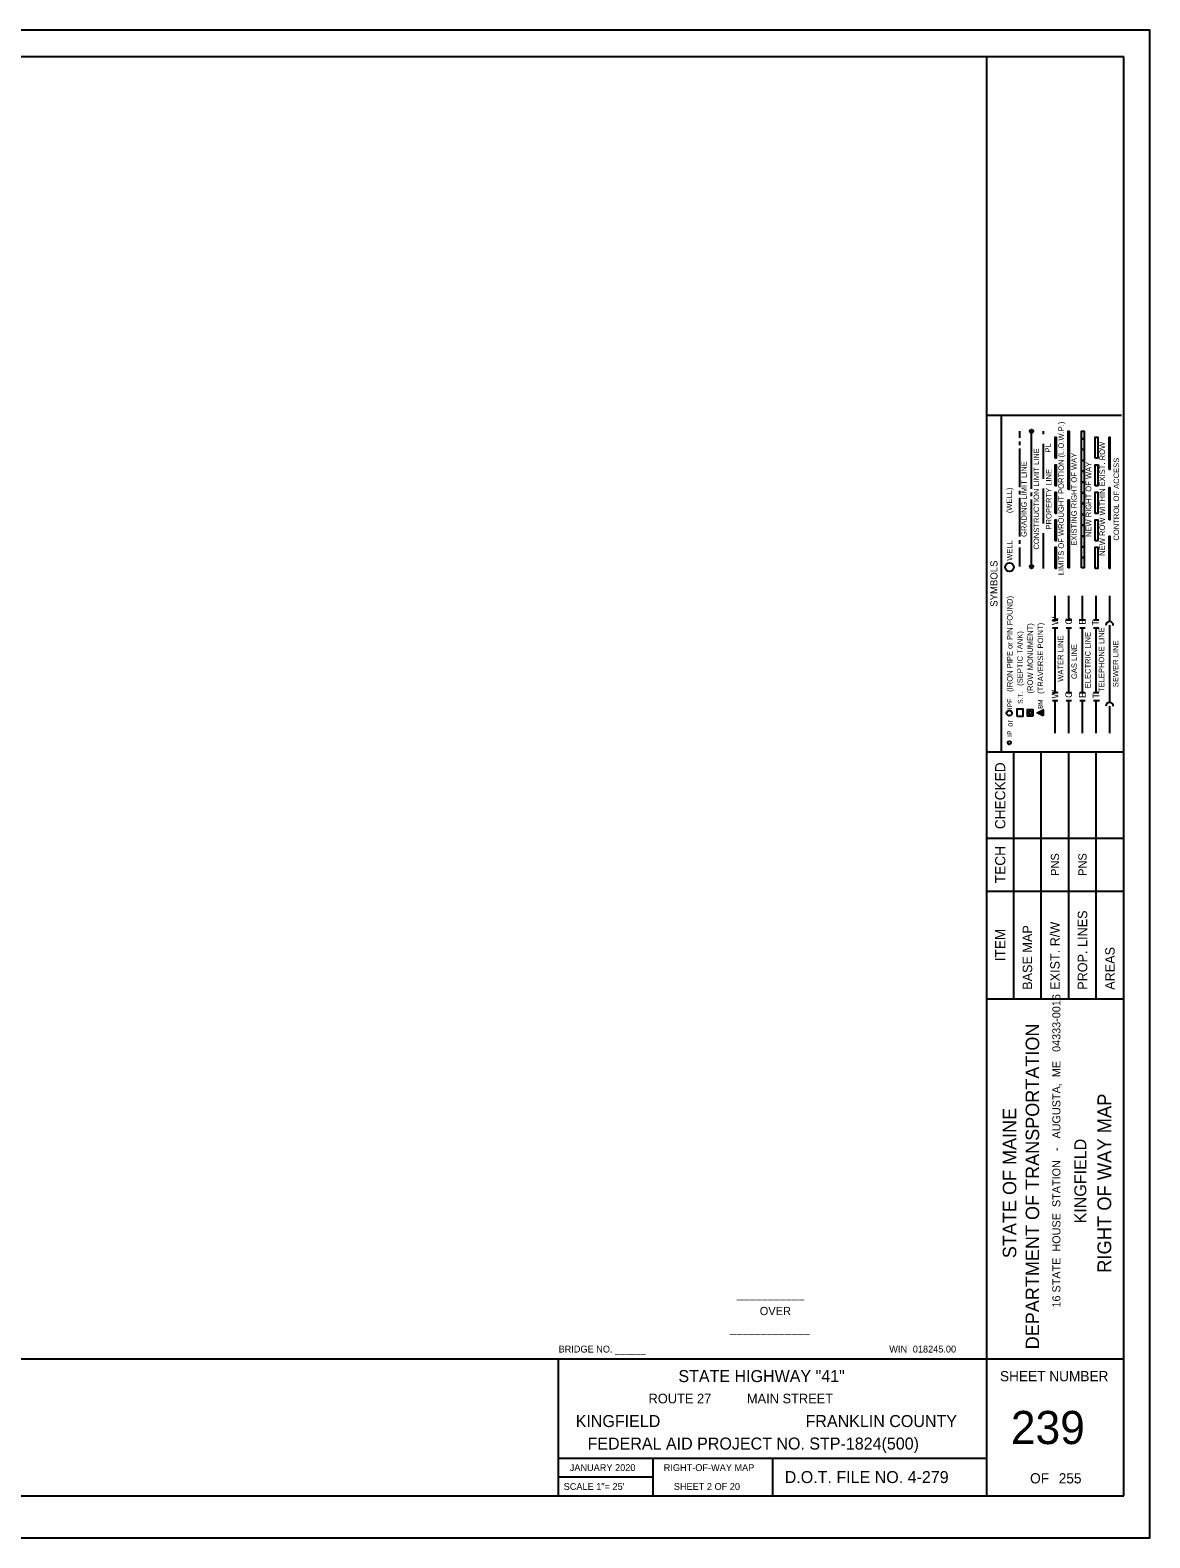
# Model space of a CAD drawing. Extents: x -415 to 435, y -303 to 247.
# Drawn here: x 26 to 435, y -303 to 247 of the extents above; entities that cross this region are included whole.
import ezdxf

# ---------------------------------------------------------------- set-up
doc = ezdxf.new("R2010")
doc.units = 0
for name, color, linetype in [('Border', 7, 'Continuous'), ('BRIDGE_TITLE', 7, 'Continuous'), ('HIGHWAY_TITLE', 7, 'Continuous'), ('PLOT BOUNDARY', 7, 'Continuous')]:
    doc.layers.add(name, color=color, linetype=linetype)

msp = doc.modelspace()

# ---------------------------------------------------------------- linework, layer by layer
at = {"layer": 'Border'}
for p, q in [((425, 237.5), (-375, 237.5)), ((375, -287.5), (375, 237.5)), ((425, -287.49), (425, 237.5)), ((375, 106.81), (424.21, 106.81)), ((380.25, 106.81), (380.25, -16.1)), ((387.03, 98.49), (387.03, 100.86)), ((391.35, 79.88), (391.35, 100.24)), ((395.67, 99.88), (395.67, 100.86)), ((387.03, 95.86), (387.03, 97.18)), ((387.03, 87.51), (387.03, 94.55)), ((395.67, 83.54), (395.67, 96.34)), ((387.03, 80.47), (387.03, 87.51)), ((387.03, 77.85), (387.03, 79.16)), ((391.35, 77.25), (391.35, 78.57)), ((395.67, 67.2), (395.67, 80)), ((387.03, 69.5), (387.03, 76.54)), ((391.35, 52.11), (391.35, 75.94)), ((387.03, 62.46), (387.03, 69.5)), ((387.03, 59.84), (387.03, 61.15)), ((395.67, 50.86), (395.67, 63.66)), ((387.03, 51.49), (387.03, 58.53)), ((399.99, 32.13), (399.99, 40.79)), ((404.97, 32.13), (404.97, 40.79)), ((409.94, 32.13), (409.94, 40.79)), ((414.92, 32.13), (414.92, 40.79)), ((419.9, 31.54), (419.9, 40.79)), ((399.01, 32.13), (400.98, 32.13)), ((399.01, 29.18), (400.98, 29.18)), ((399.99, 5.56), (399.99, 29.18)), ((403.98, 32.13), (405.95, 32.13)), ((403.98, 29.18), (405.95, 29.18)), ((404.97, 17.37), (404.97, 29.18)), ((408.96, 32.13), (410.93, 32.13)), ((408.96, 29.18), (410.93, 29.18)), ((409.94, 17.37), (409.94, 29.18)), ((413.94, 32.13), (415.9, 32.13)), ((413.94, 29.18), (415.9, 29.18)), ((414.92, 17.37), (414.92, 29.18)), ((419.9, 20.32), (419.9, 30.16)), ((404.97, 5.56), (404.97, 17.37)), ((409.94, 5.56), (409.94, 17.37)), ((414.92, 5.56), (414.92, 17.37)), ((419.9, 2.01), (419.9, 20.32)), ((399.01, 5.56), (400.98, 5.56)), ((403.98, 5.56), (405.95, 5.56)), ((408.96, 5.56), (410.93, 5.56)), ((413.94, 5.56), (415.9, 5.56)), ((399.01, 2.61), (400.98, 2.61)), ((399.99, -9.21), (399.99, 2.61)), ((403.98, 2.61), (405.95, 2.61)), ((404.97, -9.21), (404.97, 2.61)), ((408.96, 2.61), (410.93, 2.61)), ((409.94, -9.21), (409.94, 2.61)), ((413.94, 2.61), (416.1, 2.61)), ((414.92, -9.21), (414.92, 2.61)), ((419.9, -9.21), (419.9, 0.64)), ((375, -16.1), (425, -16.1)), ((384.84, -106.22), (384.84, -16.1)), ((394.88, -106.22), (394.88, -16.1)), ((404.92, -106.22), (404.92, -16.1)), ((414.96, -106.22), (414.96, -16.1)), ((375, -47.6), (425, -47.6)), ((375, -66.94), (425, -66.94)), ((375, -106.22), (425, -106.22)), ((-375, -237.49), (425, -237.49)), ((218.75, -287.5), (218.75, -237.49)), ((218.75, -273.75), (375, -273.75)), ((253.12, -273.75), (253.12, -287.5)), ((296.87, -273.75), (296.87, -287.5)), ((253.12, -280.62), (218.75, -280.62)), ((-375, -287.5), (425, -287.5))]:
    msp.add_line(p, q, dxfattribs=at)
for points in [[(404.71, 79.6), (404.71, 100.86), (405.1, 100.86), (405.1, 79.6)], [(409.62, 98.11), (409.62, 100.86), (410.6, 100.86), (410.6, 98.11)], [(399.99, 91.02), (399.99, 98.7), (400.39, 98.7), (400.39, 91.02)], [(409.62, 94.17), (409.62, 98.11), (410.6, 98.11), (410.6, 94.17)], [(409.62, 90.23), (409.62, 94.17), (410.6, 94.17), (410.6, 90.23)], [(414.59, 91.02), (414.59, 98.7), (415.58, 98.7), (415.58, 91.02)], [(419.7, 86.89), (419.7, 98.7), (419.9, 98.7), (419.9, 86.89)], [(399.99, 80.98), (399.99, 88.66), (400.39, 88.66), (400.39, 80.98)], [(409.62, 86.3), (409.62, 90.23), (410.6, 90.23), (410.6, 86.3)], [(414.59, 80.98), (414.59, 88.66), (415.58, 88.66), (415.58, 80.98)], [(409.62, 82.36), (409.62, 86.3), (410.6, 86.3), (410.6, 82.36)], [(399.99, 70.94), (399.99, 78.62), (400.39, 78.62), (400.39, 70.94)], [(409.62, 78.42), (409.62, 82.36), (410.6, 82.36), (410.6, 78.42)], [(409.62, 74.48), (409.62, 78.42), (410.6, 78.42), (410.6, 74.48)], [(414.59, 70.94), (414.59, 78.62), (415.58, 78.62), (415.58, 70.94)], [(419.7, 68.58), (419.7, 80.39), (419.9, 80.39), (419.9, 68.58)], [(404.71, 51.06), (404.71, 75.86), (405.1, 75.86), (405.1, 51.06)], [(409.62, 70.55), (409.62, 74.48), (410.6, 74.48), (410.6, 70.55)], [(399.99, 60.9), (399.99, 68.58), (400.39, 68.58), (400.39, 60.9)], [(409.62, 66.61), (409.62, 70.55), (410.6, 70.55), (410.6, 66.61)], [(409.62, 62.67), (409.62, 66.61), (410.6, 66.61), (410.6, 62.67)], [(414.59, 60.9), (414.59, 68.58), (415.58, 68.58), (415.58, 60.9)], [(409.62, 58.74), (409.62, 62.67), (410.6, 62.67), (410.6, 58.74)], [(419.7, 50.86), (419.7, 62.67), (419.9, 62.67), (419.9, 50.86)], [(399.99, 50.86), (399.99, 58.54), (400.39, 58.54), (400.39, 50.86)], [(409.62, 54.8), (409.62, 58.74), (410.6, 58.74), (410.6, 54.8)], [(414.59, 50.86), (414.59, 58.54), (415.58, 58.54), (415.58, 50.86)], [(409.62, 51.06), (409.62, 54.8), (410.6, 54.8), (410.6, 51.06)]]:
    msp.add_lwpolyline(points, close=True, dxfattribs=at)
for points in [[(385.95, -3.1), (388.31, -3.1), (388.31, -0.54), (385.95, -0.54), (385.95, -3.1)], [(391.98, -2.95), (391.98, -0.7), (389.73, -0.7), (389.73, -2.95), (391.98, -2.95)], [(395.54, -2.89), (393.44, -1.83), (395.54, -0.78), (395.54, -2.89)]]:
    msp.add_lwpolyline(points, dxfattribs=at)
for centre, radius in [((391.35, 100.86), 0.625), ((391.35, 100.86), 0.15), ((391.35, 100.86), 0.05), ((383.29, 51.3), 1.57), ((391.35, 51.49), 0.625), ((391.35, 51.49), 0.15), ((391.35, 51.49), 0.05), ((383.24, -1.91), 0.966), ((390.86, -1.82), 0.563), ((394.86, -1.82), 0.281), ((383.24, -12.74), 0.625)]:
    msp.add_circle(centre, radius, dxfattribs=at)
for centre in [(419.84, 30.08), (419.84, 0.56)]:
    msp.add_arc(centre, 1.35, 0, 180, dxfattribs=at)
at = {"layer": 'PLOT BOUNDARY'}
msp.add_lwpolyline([(-415.47, -302.8), (434.53, -302.8), (434.53, 247.2), (-415.47, 247.2)], close=True, dxfattribs=at)

# ---------------------------------------------------------------- texts
at = {"layer": 'Border'}
for s, height, rotation, p in [('LIMITS OF WROUGHT PORTION (L.O.W.P.)', 1.9996, 90, (403.14, 48.4)), ('PL', 2, 90, (398.35, 93.09)), ('NEW ROW WITHIN EXIST. ROW', 1.9996, 90, (418.14, 55.45)), ('GRADING LIMIT LINE', 1.9996, 90, (389.59, 62.32)), ('CONSTRUCTION LIMIT LINE', 1.9996, 90, (394.11, 57.72)), ('EXISTING RIGHT OF WAY', 1.9996, 90, (407.86, 59.13)), ('NEW RIGHT OF WAY', 1.9996, 90, (413.16, 62.28)), ('CONTROL OF ACCESS', 1.9996, 90, (423.29, 61)), ('PROPERTY LINE', 1.9996, 90, (398.63, 65.04)), ('(WELL)', 2, 90, (384.23, 71.01)), ('WELL', 1.969, 90, (384.36, 53.66)), ('SYMBOLS', 2.614, 90, (378.93, 36.84)), ('(IRON PIPE or PIN FOUND)', 1.9996, 90, (384.41, 5.83)), ('W', 2.46, 90, (401.17, 30.16)), ('(ROW MONUMENT)', 1.9996, 90, (391.85, 5.23)), ('(TRAVERSE POINT)', 1.9996, 90, (395.58, 5.08)), ('G', 2.46, 90, (406.15, 30.36)), ('E', 2.46, 90, (411.13, 30.36)), ('T', 2.46, 90, (415.9, 29.97)), ('TELEPHONE LINE', 1.9996, 90, (417.87, 5.75)), ('(SEPTIC TANK)', 1.9996, 90, (388.13, 8.02)), ('WATER LINE', 2, 90, (402.95, 9.5)), ('GAS LINE', 2, 90, (407.92, 10.48)), ('ELECTRIC LINE', 1.9996, 90, (412.9, 7.13)), ('SEWER LINE', 2, 90, (423.05, 7.53)), ('W', 2.46, 90, (401.17, 3.39)), ('G', 2.46, 90, (406.15, 3.59)), ('E', 2.46, 90, (411.13, 3.59)), ('IPF', 1.749, 90, (384.28, -0.48)), ('S.T.', 1.749, 90, (388.12, 1.42)), ('BM', 1.641, 90, (395.4, -0.38)), ('T', 2.46, 90, (416.1, 3.39)), ('or', 2, 90, (384.47, -6.92)), ('IP', 1.749, 90, (384.28, -10.58)), ('CHECKED', 3.726, 90, (381.78, -44.27)), ('TECH', 3.726, 90, (381.78, -63.99)), ('PROP. LINES', 3.4449, 90, (411.66, -102.87)), ('ITEM', 3.726, 90, (381.78, -92.49)), ('BASE MAP', 3.445, 90, (391.58, -102.87)), ('EXIST. R/W', 3.445, 90, (401.62, -102.87)), ('AREAS', 3.445, 90, (421.7, -102.87)), ('16 STATE  HOUSE  STATION   -   AUGUSTA,  ME   04333-0016', 2.9528, 90, (401.89, -218.78)), ('DEPARTMENT OF TRANSPORTATION', 4.9217, 90, (394.13, -234.02)), ('RIGHT OF WAY MAP', 4.9996, 90, (420.42, -206.11)), ('STATE OF MAINE', 4.9217, 90, (385.79, -200.78)), ('D.O.T. FILE NO. 4-279', 4.375, 360, (301.28, -282.81))]:
    msp.add_text(s, height=height, rotation=rotation, dxfattribs=at).set_placement(p)
for s, height, p in [('SHEET NUMBER', 3.7264, (379.83, -245.67)), ('239', 12.097, (383.82, -268.59)), ('OF', 3.726, (390.83, -282.94)), ('255', 3.726, (401.28, -282.94))]:
    msp.add_text(s, height=height, dxfattribs=at).set_placement(p)
at = {"layer": 'BRIDGE_TITLE'}
for s, height, p in [('___________', 3, (283.84, -215.3)), ('OVER', 3, (292.18, -221.55)), ('_____________', 3, (281.29, -227.8)), ('BRIDGE NO. ______', 2.5, (218.75, -235.19))]:
    msp.add_text(s, height=height, dxfattribs=at).set_placement(p)
at = {"layer": 'HIGHWAY_TITLE'}
for s, height, rotation, p in [('PNS', 3, 90, (401.4, -61.3)), ('PNS', 3, 90, (411.44, -61.3)), ('KINGFIELD', 4.375, 90, (411.35, -188.1)), ('SCALE 1"= 25\'', 2.5, 360, (220.61, -285.31))]:
    msp.add_text(s, height=height, rotation=rotation, dxfattribs=at).set_placement(p)
for s, height, p in [('WIN', 2.5, (339.44, -235.19)), ('018245.00', 2.5, (348.02, -235.19)), ('STATE HIGHWAY "41"', 4.375, (262.49, -245.97)), ('ROUTE 27          MAIN STREET', 3.5, (251.59, -253.73)), ('KINGFIELD', 4.375, (225, -262.38)), ('FRANKLIN COUNTY', 4.375, (308.88, -262.38)), ('FEDERAL AID PROJECT NO. STP-1824(500)', 4.375, (229.33, -270.58)), ('JANUARY 2020', 2.5, (222.83, -278.43)), ('RIGHT-OF-WAY MAP', 2.5, (257.13, -278.43)), ('SHEET 2 OF 20', 2.5, (260.81, -285.31))]:
    msp.add_text(s, height=height, dxfattribs=at).set_placement(p)

doc.saveas('drawing.dxf')
